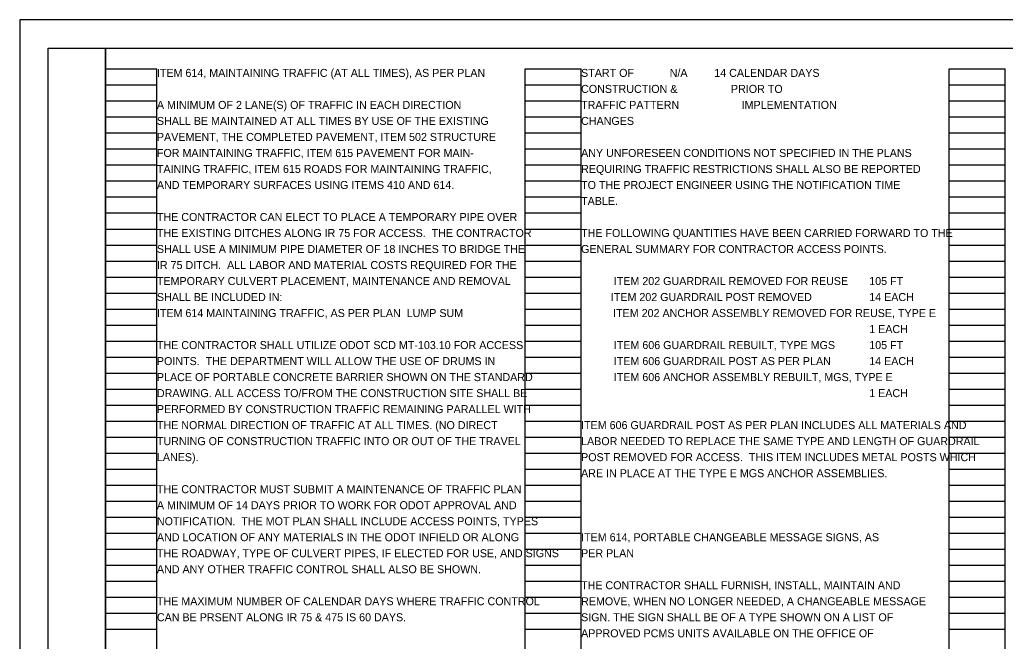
# Model space of a CAD drawing. Extents: x 0 to 34, y 0 to 22.
# Drawn here: x 0 to 17.24, y 11.13 to 22 of the extents above; entities that cross this region are included whole.
import ezdxf

# ---------------------------------------------------------------- set-up
doc = ezdxf.new("R2010")
doc.units = 0
for name, color, linetype in [('SH_Border', 7, 'Continuous'), ('SH_Cut_Line', 7, 'Continuous'), ('SH_Data', 7, 'Continuous'), ('SH_Text', 7, 'Continuous')]:
    doc.layers.add(name, color=color, linetype=linetype)

msp = doc.modelspace()

# ---------------------------------------------------------------- linework, layer by layer
at = {"layer": 'SH_Border'}
for points in [[(0.5, 21.5), (1.5, 21.5), (1.5, 0.5), (0.5, 0.5)], [(1.5, 21.5), (33.5, 21.5), (33.5, 0.5), (1.5, 0.5)]]:
    msp.add_lwpolyline(points, close=True, dxfattribs=at)
at = {"layer": 'SH_Cut_Line'}
msp.add_lwpolyline([(0, 0), (34, 0), (34, 22), (0, 22)], close=True, dxfattribs=at)
at = {"layer": 'SH_Data'}
for p, q in [((1.5, 0.98), (1.5, 21.14)), ((1.5, 21.14), (2.4, 21.14)), ((2.4, 0.98), (2.4, 21.14)), ((8.84, 0.98), (8.84, 21.14)), ((8.84, 21.14), (9.82, 21.14)), ((9.82, 0.98), (9.82, 21.14)), ((16.26, 0.98), (16.26, 21.14)), ((16.26, 21.14), (17.24, 21.14)), ((17.24, 0.98), (17.24, 21.14)), ((1.5, 20.86), (2.4, 20.86)), ((8.84, 20.86), (9.82, 20.86)), ((16.26, 20.86), (17.24, 20.86)), ((1.5, 20.58), (2.4, 20.58)), ((8.84, 20.58), (9.82, 20.58)), ((16.26, 20.58), (17.24, 20.58)), ((1.5, 20.3), (2.4, 20.3)), ((8.84, 20.3), (9.82, 20.3)), ((16.26, 20.3), (17.24, 20.3)), ((1.5, 20.02), (2.4, 20.02)), ((8.84, 20.02), (9.82, 20.02)), ((16.26, 20.02), (17.24, 20.02)), ((1.5, 19.74), (2.4, 19.74)), ((8.84, 19.74), (9.82, 19.74)), ((16.26, 19.74), (17.24, 19.74)), ((1.5, 19.46), (2.4, 19.46)), ((8.84, 19.46), (9.82, 19.46)), ((16.26, 19.46), (17.24, 19.46)), ((1.5, 19.18), (2.4, 19.18)), ((8.84, 19.18), (9.82, 19.18)), ((16.26, 19.18), (17.24, 19.18)), ((1.5, 18.9), (2.4, 18.9)), ((8.84, 18.9), (9.82, 18.9)), ((16.26, 18.9), (17.24, 18.9)), ((1.5, 18.62), (2.4, 18.62)), ((8.84, 18.62), (9.82, 18.62)), ((16.26, 18.62), (17.24, 18.62)), ((1.5, 18.34), (2.4, 18.34)), ((8.84, 18.34), (9.82, 18.34)), ((16.26, 18.34), (17.24, 18.34)), ((1.5, 18.06), (2.4, 18.06)), ((8.84, 18.06), (9.82, 18.06)), ((16.26, 18.06), (17.24, 18.06)), ((1.5, 17.78), (2.4, 17.78)), ((8.84, 17.78), (9.82, 17.78)), ((16.26, 17.78), (17.24, 17.78)), ((1.5, 17.5), (2.4, 17.5)), ((8.84, 17.5), (9.82, 17.5)), ((16.26, 17.5), (17.24, 17.5)), ((1.5, 17.22), (2.4, 17.22)), ((8.84, 17.22), (9.82, 17.22)), ((16.26, 17.22), (17.24, 17.22)), ((1.5, 16.94), (2.4, 16.94)), ((8.84, 16.94), (9.82, 16.94)), ((16.26, 16.94), (17.24, 16.94)), ((1.5, 16.66), (2.4, 16.66)), ((8.84, 16.66), (9.82, 16.66)), ((16.26, 16.66), (17.24, 16.66)), ((1.5, 16.38), (2.4, 16.38)), ((8.84, 16.38), (9.82, 16.38)), ((16.26, 16.38), (17.24, 16.38)), ((1.5, 16.1), (2.4, 16.1)), ((8.84, 16.1), (9.82, 16.1)), ((16.26, 16.1), (17.24, 16.1)), ((1.5, 15.82), (2.4, 15.82)), ((8.84, 15.82), (9.82, 15.82)), ((16.26, 15.82), (17.24, 15.82)), ((1.5, 15.54), (2.4, 15.54)), ((8.84, 15.54), (9.82, 15.54)), ((16.26, 15.54), (17.24, 15.54)), ((1.5, 15.26), (2.4, 15.26)), ((8.84, 15.26), (9.82, 15.26)), ((16.26, 15.26), (17.24, 15.26)), ((1.5, 14.98), (2.4, 14.98)), ((8.84, 14.98), (9.82, 14.98)), ((16.26, 14.98), (17.24, 14.98)), ((1.5, 14.7), (2.4, 14.7)), ((8.84, 14.7), (9.82, 14.7)), ((16.26, 14.7), (17.24, 14.7)), ((1.5, 14.42), (2.4, 14.42)), ((8.84, 14.42), (9.82, 14.42)), ((16.26, 14.42), (17.24, 14.42)), ((1.5, 14.14), (2.4, 14.14)), ((8.84, 14.14), (9.82, 14.14)), ((16.26, 14.14), (17.24, 14.14)), ((1.5, 13.86), (2.4, 13.86)), ((8.84, 13.86), (9.82, 13.86)), ((16.26, 13.86), (17.24, 13.86)), ((1.5, 13.58), (2.4, 13.58)), ((8.84, 13.58), (9.82, 13.58)), ((16.26, 13.58), (17.24, 13.58)), ((1.5, 13.3), (2.4, 13.3)), ((8.84, 13.3), (9.82, 13.3)), ((16.26, 13.3), (17.24, 13.3)), ((1.5, 13.02), (2.4, 13.02)), ((8.84, 13.02), (9.82, 13.02)), ((16.26, 13.02), (17.24, 13.02)), ((1.5, 12.74), (2.4, 12.74)), ((8.84, 12.74), (9.82, 12.74)), ((16.26, 12.74), (17.24, 12.74)), ((1.5, 12.46), (2.4, 12.46)), ((8.84, 12.46), (9.82, 12.46)), ((16.26, 12.46), (17.24, 12.46)), ((1.5, 12.18), (2.4, 12.18)), ((8.84, 12.18), (9.82, 12.18)), ((16.26, 12.18), (17.24, 12.18)), ((1.5, 11.9), (2.4, 11.9)), ((8.84, 11.9), (9.82, 11.9)), ((16.26, 11.9), (17.24, 11.9)), ((1.5, 11.62), (2.4, 11.62)), ((8.84, 11.62), (9.82, 11.62)), ((16.26, 11.62), (17.24, 11.62)), ((1.5, 11.34), (2.4, 11.34)), ((8.84, 11.34), (9.82, 11.34)), ((16.26, 11.34), (17.24, 11.34))]:
    msp.add_line(p, q, dxfattribs=at)

# ---------------------------------------------------------------- texts
at = {"layer": 'SH_Text'}
for s, p in [('ITEM 614, MAINTAINING TRAFFIC (AT ALL TIMES), AS PER PLAN', (2.4, 21)), ('START OF            N/A         14 CALENDAR DAYS', (9.82, 21)), ('CONSTRUCTION &                  PRIOR TO', (9.82, 20.72)), ('A MINIMUM OF 2 LANE(S) OF TRAFFIC IN EACH DIRECTION', (2.4, 20.44)), ('TRAFFIC PATTERN                     IMPLEMENTATION', (9.82, 20.44)), ('SHALL BE MAINTAINED AT ALL TIMES BY USE OF THE EXISTING', (2.4, 20.16)), ('CHANGES', (9.82, 20.16)), ('PAVEMENT, THE COMPLETED PAVEMENT, ITEM 502 STRUCTURE', (2.4, 19.88)), ('FOR MAINTAINING TRAFFIC, ITEM 615 PAVEMENT FOR MAIN-', (2.4, 19.6)), ('ANY UNFORESEEN CONDITIONS NOT SPECIFIED IN THE PLANS', (9.82, 19.6)), ('TAINING TRAFFIC, ITEM 615 ROADS FOR MAINTAINING TRAFFIC,', (2.4, 19.32)), ('REQUIRING TRAFFIC RESTRICTIONS SHALL ALSO BE REPORTED', (9.82, 19.32)), ('AND TEMPORARY SURFACES USING ITEMS 410 AND 614.', (2.4, 19.04)), ('TO THE PROJECT ENGINEER USING THE NOTIFICATION TIME', (9.82, 19.04)), ('TABLE.', (9.82, 18.76)), ('THE CONTRACTOR CAN ELECT TO PLACE A TEMPORARY PIPE OVER ', (2.4, 18.48)), ('THE EXISTING DITCHES ALONG IR 75 FOR ACCESS.  THE CONTRACTOR ', (2.4, 18.2)), ('THE FOLLOWING QUANTITIES HAVE BEEN CARRIED FORWARD TO THE ', (9.82, 18.2)), ('SHALL USE A MINIMUM PIPE DIAMETER OF 18 INCHES TO BRIDGE THE ', (2.4, 17.92)), ('GENERAL SUMMARY FOR CONTRACTOR ACCESS POINTS.', (9.82, 17.92)), ('IR 75 DITCH.  ALL LABOR AND MATERIAL COSTS REQUIRED FOR THE', (2.4, 17.64)), ('TEMPORARY CULVERT PLACEMENT, MAINTENANCE AND REMOVAL ', (2.4, 17.36)), ('           ITEM 202 GUARDRAIL REMOVED FOR REUSE', (9.82, 17.36)), ('105 FT', (14.86, 17.36)), ('SHALL BE INCLUDED IN:', (2.4, 17.08)), ('          ITEM 202 GUARDRAIL POST REMOVED', (9.82, 17.08)), ('14 EACH', (14.86, 17.08)), ('ITEM 614 MAINTAINING TRAFFIC, AS PER PLAN  LUMP SUM', (2.4, 16.8)), ('ITEM 202 ANCHOR ASSEMBLY REMOVED FOR REUSE, TYPE E', (10.38, 16.8)), ('1 EACH', (14.86, 16.52)), ('THE CONTRACTOR SHALL UTILIZE ODOT SCD MT-103.10 FOR ACCESS', (2.4, 16.24)), ('           ITEM 606 GUARDRAIL REBUILT, TYPE MGS', (9.82, 16.24)), ('105 FT', (14.86, 16.24)), ('POINTS.  THE DEPARTMENT WILL ALLOW THE USE OF DRUMS IN', (2.4, 15.96)), ('           ITEM 606 GUARDRAIL POST AS PER PLAN', (9.82, 15.96)), ('14 EACH', (14.86, 15.96)), ('PLACE OF PORTABLE CONCRETE BARRIER SHOWN ON THE STANDARD', (2.4, 15.68)), ('           ITEM 606 ANCHOR ASSEMBLY REBUILT, MGS, TYPE E', (9.82, 15.68)), ('DRAWING. ', (2.4, 15.4)), ('ALL ACCESS TO/FROM THE CONSTRUCTION SITE SHALL BE ', (3.409, 15.4)), ('1 EACH', (14.86, 15.4)), ('PERFORMED BY CONSTRUCTION TRAFFIC REMAINING PARALLEL WITH ', (2.4, 15.12)), ('THE NORMAL DIRECTION OF TRAFFIC AT ALL TIMES. (NO DIRECT ', (2.4, 14.84)), ('ITEM 606 GUARDRAIL POST AS PER PLAN INCLUDES ALL MATERIALS AND ', (9.82, 14.84)), ('TURNING OF CONSTRUCTION TRAFFIC INTO OR OUT OF THE TRAVEL', (2.4, 14.56)), ('LABOR NEEDED TO REPLACE THE SAME TYPE AND LENGTH OF GUARDRAIL ', (9.82, 14.56)), ('LANES).', (2.4, 14.28)), ('POST REMOVED FOR ACCESS.  THIS ITEM INCLUDES METAL POSTS WHICH ', (9.82, 14.28)), ('ARE IN PLACE AT THE TYPE E MGS ANCHOR ASSEMBLIES.', (9.82, 14)), ('THE CONTRACTOR MUST SUBMIT A MAINTENANCE OF TRAFFIC PLAN', (2.4, 13.72)), ('A MINIMUM OF 14 DAYS PRIOR TO WORK FOR ODOT APPROVAL AND ', (2.4, 13.44)), ('NOTIFICATION.  THE MOT PLAN SHALL INCLUDE ACCESS POINTS, TYPES', (2.4, 13.16)), ('AND LOCATION OF ANY MATERIALS IN THE ODOT INFIELD OR ALONG ', (2.4, 12.88)), ('ITEM 614, PORTABLE CHANGEABLE MESSAGE SIGNS, AS', (9.82, 12.88)), ('THE ROADWAY, TYPE OF CULVERT PIPES, IF ELECTED FOR USE, AND SIGNS ', (2.4, 12.6)), ('PER PLAN', (9.82, 12.6)), ('AND ANY OTHER TRAFFIC CONTROL SHALL ALSO BE SHOWN.', (2.4, 12.32)), ('THE CONTRACTOR SHALL FURNISH, INSTALL, MAINTAIN AND', (9.82, 12.04)), ('THE MAXIMUM NUMBER OF CALENDAR DAYS WHERE TRAFFIC CONTROL ', (2.4, 11.76)), ('REMOVE, WHEN NO LONGER NEEDED, A CHANGEABLE MESSAGE', (9.82, 11.76)), ('CAN BE PRSENT ALONG IR 75 & 475 IS 60 DAYS.', (2.4, 11.48)), ('SIGN. THE SIGN SHALL BE OF A TYPE SHOWN ON A LIST OF', (9.82, 11.48)), ('APPROVED PCMS UNITS AVAILABLE ON THE OFFICE OF', (9.82, 11.2))]:
    msp.add_text(s, height=0.14, dxfattribs=at).set_placement(p)

doc.saveas('drawing.dxf')
